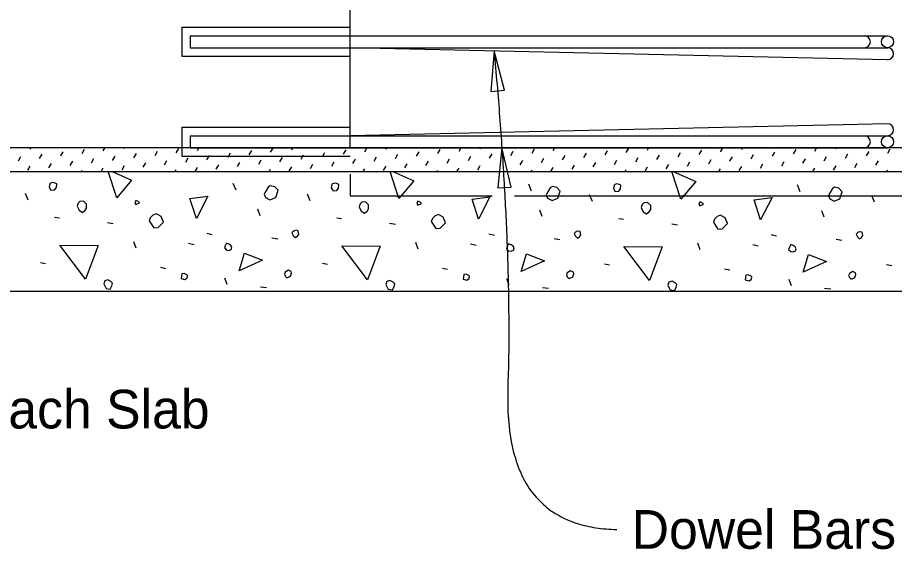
# Model space of a CAD drawing. Extents: x 21665 to 21741.5, y 56121.9 to 56164.2.
# Drawn here: x 21705.4 to 21709.972, y 56139.518 to 56142.347 of the extents above; entities that cross this region are included whole.
import ezdxf

# ---------------------------------------------------------------- set-up
doc = ezdxf.new("R2010")
doc.units = 0
for name, color, linetype in [('Dimension', 7, 'Continuous'), ('ExistSuperStruct', 7, 'Continuous'), ('Miscellaneous', 7, 'Continuous'), ('Rebar', 7, 'Continuous'), ('StrMiscConc', 7, 'Continuous'), ('StrMiscConc_h', 7, 'Continuous'), ('TextStructures', 7, 'Continuous')]:
    doc.layers.add(name, color=color, linetype=linetype)

msp = doc.modelspace()

# ---------------------------------------------------------------- linework, layer by layer
at = {"layer": 'Dimension'}
for points in [[(21707.8847, 56142.1727), (21707.8687, 56141.9621), (21707.939, 56141.9686)], [(21707.9254, 56141.6688), (21707.904, 56141.4586), (21707.9744, 56141.4633)]]:
    msp.add_lwpolyline(points, close=True, dxfattribs=at)
msp.add_open_spline([(21707.8847, 56142.1727), (21707.9806, 56141.1325), (21707.9326, 56139.6921), (21708.5241, 56139.6796)], degree=2, dxfattribs=at)
at = {"layer": 'ExistSuperStruct'}
for p, q in [((21706.2561, 56142.2964), (21706.2561, 56142.145)), ((21706.2561, 56142.2964), (21707.1339, 56142.2964)), ((21706.2561, 56142.145), (21707.1339, 56142.145)), ((21706.2561, 56141.7755), (21706.2561, 56141.6241)), ((21706.2561, 56141.7755), (21707.1339, 56141.7755)), ((21699.1314, 56141.6687), (21711.5431, 56141.6687)), ((21706.2561, 56141.6241), (21707.1339, 56141.6241)), ((21699.1314, 56141.5437), (21711.5431, 56141.5437)), ((21711.5431, 56140.9187), (21704.3514, 56140.9187))]:
    msp.add_line(p, q, dxfattribs=at)
at = {"layer": 'Miscellaneous'}
for p, q in [((21705.4666, 56141.6613), (21705.4709, 56141.6687)), ((21705.7367, 56141.6384), (21705.7496, 56141.6608)), ((21705.8473, 56141.6514), (21705.8574, 56141.6687)), ((21705.9579, 56141.6643), (21705.9605, 56141.6687)), ((21706.228, 56141.6414), (21706.241, 56141.6638)), ((21706.3387, 56141.6544), (21706.347, 56141.6687)), ((21706.4493, 56141.6673), (21706.4501, 56141.6687)), ((21706.7194, 56141.6444), (21706.7324, 56141.6668)), ((21706.83, 56141.6574), (21706.8366, 56141.6687)), ((21707.2108, 56141.6475), (21707.2231, 56141.6687)), ((21707.3214, 56141.6604), (21707.3262, 56141.6687)), ((21707.5915, 56141.6375), (21707.6045, 56141.6599)), ((21707.7021, 56141.6505), (21707.7127, 56141.6687)), ((21707.8128, 56141.6634), (21707.8158, 56141.6687)), ((21708.0829, 56141.6405), (21708.0958, 56141.6629)), ((21708.1935, 56141.6535), (21708.2023, 56141.6687)), ((21708.3041, 56141.6665), (21708.3054, 56141.6687)), ((21708.5742, 56141.6436), (21708.5872, 56141.6659)), ((21708.6849, 56141.6565), (21708.6919, 56141.6687)), ((21709.0656, 56141.6466), (21709.0784, 56141.6687)), ((21709.1762, 56141.6595), (21709.1815, 56141.6687)), ((21709.4463, 56141.6366), (21709.4593, 56141.659)), ((21709.557, 56141.6496), (21709.568, 56141.6687)), ((21709.6676, 56141.6626), (21709.6712, 56141.6687)), ((21709.9377, 56141.6397), (21709.9507, 56141.662)), ((21705.4048, 56141.5995), (21705.4177, 56141.6219)), ((21705.5154, 56141.6125), (21705.5284, 56141.6349)), ((21705.626, 56141.6254), (21705.639, 56141.6478)), ((21705.8961, 56141.6025), (21705.9091, 56141.6249)), ((21706.0068, 56141.6155), (21706.0197, 56141.6379)), ((21706.1174, 56141.6285), (21706.1304, 56141.6508)), ((21706.2769, 56141.5926), (21706.2898, 56141.615)), ((21706.3875, 56141.6055), (21706.4005, 56141.6279)), ((21706.4981, 56141.6185), (21706.5111, 56141.6409)), ((21706.6088, 56141.6315), (21706.6217, 56141.6539)), ((21706.7682, 56141.5956), (21706.7812, 56141.618)), ((21706.8789, 56141.6086), (21706.8918, 56141.631)), ((21706.9895, 56141.6215), (21707.0025, 56141.6439)), ((21707.1001, 56141.6345), (21707.1131, 56141.6569)), ((21707.2596, 56141.5986), (21707.2726, 56141.621)), ((21707.3702, 56141.6116), (21707.3832, 56141.634)), ((21707.4809, 56141.6246), (21707.4938, 56141.6469)), ((21707.751, 56141.6016), (21707.7639, 56141.624)), ((21707.8616, 56141.6146), (21707.8746, 56141.637)), ((21707.9722, 56141.6276), (21707.9852, 56141.65)), ((21708.1317, 56141.5917), (21708.1447, 56141.6141)), ((21708.2423, 56141.6047), (21708.2553, 56141.6271)), ((21708.353, 56141.6176), (21708.3659, 56141.64)), ((21708.4636, 56141.6306), (21708.4766, 56141.653)), ((21708.6231, 56141.5947), (21708.636, 56141.6171)), ((21708.7337, 56141.6077), (21708.7467, 56141.6301)), ((21708.8443, 56141.6206), (21708.8573, 56141.643)), ((21708.955, 56141.6336), (21708.9679, 56141.656)), ((21709.1144, 56141.5977), (21709.1274, 56141.6201)), ((21709.2251, 56141.6107), (21709.238, 56141.6331)), ((21709.3357, 56141.6237), (21709.3487, 56141.6461)), ((21709.6058, 56141.6008), (21709.6188, 56141.6232)), ((21709.7164, 56141.6137), (21709.7294, 56141.6361)), ((21709.8271, 56141.6267), (21709.84, 56141.6491)), ((21705.4536, 56141.5507), (21705.4666, 56141.5731)), ((21705.5642, 56141.5636), (21705.5772, 56141.586)), ((21705.6749, 56141.5766), (21705.6878, 56141.599)), ((21705.7855, 56141.5896), (21705.7985, 56141.612)), ((21705.945, 56141.5537), (21705.9579, 56141.5761)), ((21706.0556, 56141.5667), (21706.0686, 56141.589)), ((21706.1662, 56141.5796), (21706.1792, 56141.602)), ((21706.4363, 56141.5567), (21706.4493, 56141.5791)), ((21706.547, 56141.5697), (21706.5599, 56141.5921)), ((21706.6576, 56141.5826), (21706.6706, 56141.605)), ((21706.8171, 56141.5468), (21706.83, 56141.5692)), ((21706.9277, 56141.5597), (21706.9407, 56141.5821)), ((21707.0383, 56141.5727), (21707.0513, 56141.5951)), ((21707.149, 56141.5857), (21707.1619, 56141.6081)), ((21707.3084, 56141.5498), (21707.3214, 56141.5722)), ((21707.4191, 56141.5628), (21707.432, 56141.5851)), ((21707.5297, 56141.5757), (21707.5427, 56141.5981)), ((21707.6403, 56141.5887), (21707.6533, 56141.6111)), ((21707.7998, 56141.5528), (21707.8128, 56141.5752)), ((21708.0211, 56141.5787), (21708.034, 56141.6011)), ((21708.2912, 56141.5558), (21708.3041, 56141.5782)), ((21708.4018, 56141.5688), (21708.4148, 56141.5912)), ((21708.5124, 56141.5818), (21708.5254, 56141.6041)), ((21708.6719, 56141.5459), (21708.6849, 56141.5683)), ((21708.7825, 56141.5589), (21708.7955, 56141.5812)), ((21708.8932, 56141.5718), (21708.9061, 56141.5942)), ((21709.0038, 56141.5848), (21709.0168, 56141.6072)), ((21709.1633, 56141.5489), (21709.1762, 56141.5713)), ((21709.2739, 56141.5619), (21709.2869, 56141.5843)), ((21709.3845, 56141.5748), (21709.3975, 56141.5972)), ((21709.4952, 56141.5878), (21709.5081, 56141.6102)), ((21709.6546, 56141.5519), (21709.6676, 56141.5743)), ((21709.7653, 56141.5649), (21709.7782, 56141.5873)), ((21709.8759, 56141.5779), (21709.8889, 56141.6002)), ((21705.7329, 56141.5437), (21705.7367, 56141.5502)), ((21705.836, 56141.5437), (21705.8473, 56141.5631)), ((21706.2225, 56141.5437), (21706.228, 56141.5532)), ((21706.3257, 56141.5438), (21706.3387, 56141.5661)), ((21706.7121, 56141.5437), (21706.7194, 56141.5562)), ((21707.0986, 56141.5437), (21707.1001, 56141.5463)), ((21707.2018, 56141.5437), (21707.2108, 56141.5592)), ((21707.5882, 56141.5437), (21707.5915, 56141.5493)), ((21707.6914, 56141.5437), (21707.7021, 56141.5622)), ((21708.0779, 56141.5437), (21708.0829, 56141.5523)), ((21708.181, 56141.5437), (21708.1935, 56141.5653)), ((21708.5675, 56141.5437), (21708.5742, 56141.5553)), ((21708.954, 56141.5437), (21708.955, 56141.5454)), ((21709.0571, 56141.5437), (21709.0656, 56141.5583)), ((21709.4436, 56141.5437), (21709.4463, 56141.5484)), ((21709.5467, 56141.5437), (21709.557, 56141.5614)), ((21709.7372, 56141.5402), (21709.7358, 56141.5437)), ((21709.9332, 56141.5437), (21709.9377, 56141.5514)), ((21706.5396, 56141.4465), (21706.5254, 56141.4818)), ((21708.0798, 56141.4429), (21708.0657, 56141.4783)), ((21705.456, 56141.3953), (21705.4418, 56141.4306)), ((21709.4808, 56141.4394), (21709.4667, 56141.4748)), ((21706.9266, 56141.3918), (21706.9125, 56141.4271)), ((21708.3973, 56141.3882), (21708.3831, 56141.4236)), ((21709.8679, 56141.3847), (21709.8538, 56141.42)), ((21706.6651, 56141.3139), (21706.6527, 56141.3475)), ((21708.1357, 56141.3104), (21708.1233, 56141.3439)), ((21709.6063, 56141.3068), (21709.594, 56141.3404)), ((21705.5939, 56141.3069), (21705.6186, 56141.3034)), ((21707.0645, 56141.3034), (21707.0893, 56141.2998)), ((21708.5351, 56141.2998), (21708.5599, 56141.2963)), ((21705.8696, 56141.2786), (21705.8997, 56141.2733)), ((21707.3403, 56141.2751), (21707.3703, 56141.2698)), ((21708.8109, 56141.2715), (21708.841, 56141.2662)), ((21706.3875, 56141.2237), (21706.4158, 56141.2167)), ((21707.8582, 56141.2202), (21707.8864, 56141.2131)), ((21709.3288, 56141.2167), (21709.3571, 56141.2096)), ((21706.0181, 56141.1443), (21706.0058, 56141.1779)), ((21706.2921, 56141.1708), (21706.3204, 56141.1637)), ((21706.7269, 56141.1991), (21706.7569, 56141.1938)), ((21707.4888, 56141.1407), (21707.4764, 56141.1743)), ((21707.7628, 56141.1672), (21707.7911, 56141.1602)), ((21708.1975, 56141.1955), (21708.2276, 56141.1902)), ((21708.9594, 56141.1372), (21708.947, 56141.1708)), ((21709.2334, 56141.1637), (21709.2617, 56141.1566)), ((21709.6681, 56141.192), (21709.6982, 56141.1867)), ((21705.5196, 56141.07), (21705.5461, 56141.0647)), ((21706.9903, 56141.0665), (21707.0168, 56141.0612)), ((21706.1454, 56141.0453), (21706.1719, 56141.04)), ((21707.6161, 56141.0417), (21707.6426, 56141.0364)), ((21708.4609, 56141.0629), (21708.4874, 56141.0576)), ((21709.0867, 56141.0382), (21709.1132, 56141.0329)), ((21709.9315, 56141.0594), (21709.9581, 56141.0541)), ((21706.4936, 56140.9552), (21706.4812, 56140.9888)), ((21707.9642, 56140.9517), (21707.9519, 56140.9852)), ((21709.4349, 56140.9481), (21709.4225, 56140.9817)), ((21706.6668, 56140.9445), (21706.6986, 56140.941)), ((21708.1374, 56140.941), (21708.1692, 56140.9374)), ((21709.608, 56140.9374), (21709.6399, 56140.9339))]:
    msp.add_line(p, q, dxfattribs=at)
for points in [[(21705.9174, 56141.4077), (21705.8731, 56141.5437)], [(21705.8942, 56141.5437), (21705.9952, 56141.4996), (21705.9174, 56141.4077)], [(21707.388, 56141.4041), (21707.3426, 56141.5437)], [(21707.3567, 56141.5437), (21707.4658, 56141.496), (21707.388, 56141.4041)], [(21708.8586, 56141.4006), (21708.8121, 56141.5437)], [(21708.8193, 56141.5437), (21708.9364, 56141.4925), (21708.8586, 56141.4006)], [(21705.5656, 56141.4625), (21705.5744, 56141.4466), (21705.5939, 56141.4483), (21705.6027, 56141.4607), (21705.6045, 56141.4801), (21705.5921, 56141.4854), (21705.5833, 56141.4872), (21705.5727, 56141.4837), (21705.5691, 56141.4801), (21705.5656, 56141.4625)], [(21707.0362, 56141.4589), (21707.0451, 56141.443), (21707.0645, 56141.4448), (21707.0733, 56141.4572), (21707.0751, 56141.4766), (21707.0627, 56141.4819), (21707.0539, 56141.4837), (21707.0433, 56141.4801), (21707.0398, 56141.4766), (21707.0362, 56141.4589)], [(21708.5069, 56141.4554), (21708.5157, 56141.4395), (21708.5351, 56141.4412), (21708.544, 56141.4536), (21708.5458, 56141.4731), (21708.5334, 56141.4784), (21708.5245, 56141.4801), (21708.5139, 56141.4766), (21708.5104, 56141.4731), (21708.5069, 56141.4554)], [(21706.6934, 56141.4094), (21706.7163, 56141.397), (21706.7464, 56141.4094), (21706.7588, 56141.4465), (21706.7411, 56141.4642), (21706.7181, 56141.4695), (21706.7075, 56141.4624), (21706.6951, 56141.4429), (21706.6863, 56141.427), (21706.6934, 56141.4094)], [(21708.164, 56141.4058), (21708.187, 56141.3934), (21708.217, 56141.4058), (21708.2294, 56141.4429), (21708.2117, 56141.4606), (21708.1887, 56141.4659), (21708.1781, 56141.4589), (21708.1658, 56141.4394), (21708.1569, 56141.4235), (21708.164, 56141.4058)], [(21709.6346, 56141.4023), (21709.6576, 56141.3899), (21709.6877, 56141.4023), (21709.7, 56141.4394), (21709.6824, 56141.4571), (21709.6594, 56141.4624), (21709.6488, 56141.4553), (21709.6364, 56141.4359), (21709.6276, 56141.42), (21709.6346, 56141.4023)], [(21705.7105, 56141.3635), (21705.7212, 56141.3423), (21705.7388, 56141.3316), (21705.753, 56141.3423), (21705.76, 56141.3529), (21705.76, 56141.3741), (21705.7441, 56141.39), (21705.7247, 56141.3882), (21705.7159, 56141.3794), (21705.7105, 56141.3635)], [(21706.0164, 56141.3723), (21706.0358, 56141.3811), (21706.0287, 56141.3882), (21706.0164, 56141.3935), (21706.0111, 56141.3811), (21706.0164, 56141.3723)], [(21706.3327, 56141.2998), (21706.2991, 56141.4041), (21706.3928, 56141.4164), (21706.3327, 56141.2998)], [(21707.1812, 56141.3599), (21707.1918, 56141.3387), (21707.2095, 56141.3281), (21707.2236, 56141.3387), (21707.2307, 56141.3493), (21707.2307, 56141.3705), (21707.2148, 56141.3864), (21707.1953, 56141.3847), (21707.1865, 56141.3758), (21707.1812, 56141.3599)], [(21707.487, 56141.3688), (21707.5065, 56141.3776), (21707.4994, 56141.3847), (21707.487, 56141.39), (21707.4817, 56141.3776), (21707.487, 56141.3688)], [(21707.8034, 56141.2962), (21707.7698, 56141.4005), (21707.8635, 56141.4129), (21707.8034, 56141.2962)], [(21708.9576, 56141.3652), (21708.9771, 56141.3741), (21708.97, 56141.3811), (21708.9576, 56141.3864), (21708.9523, 56141.3741), (21708.9576, 56141.3652)], [(21709.274, 56141.2927), (21709.2404, 56141.397), (21709.3341, 56141.4094), (21709.274, 56141.2927)], [(21708.6518, 56141.3564), (21708.6624, 56141.3352), (21708.6801, 56141.3246), (21708.6942, 56141.3352), (21708.7013, 56141.3458), (21708.7013, 56141.367), (21708.6854, 56141.3829), (21708.666, 56141.3811), (21708.6571, 56141.3723), (21708.6518, 56141.3564)], [(21706.0871, 56141.2875), (21706.1101, 56141.2503), (21706.133, 56141.2521), (21706.1419, 56141.2609), (21706.1613, 56141.2804), (21706.149, 56141.3104), (21706.1242, 56141.3246), (21706.1065, 56141.3175), (21706.0924, 56141.3034), (21706.0871, 56141.2875)], [(21707.5577, 56141.2839), (21707.5807, 56141.2468), (21707.6037, 56141.2486), (21707.6125, 56141.2574), (21707.632, 56141.2768), (21707.6196, 56141.3069), (21707.5948, 56141.321), (21707.5772, 56141.314), (21707.563, 56141.2998), (21707.5577, 56141.2839)], [(21709.0284, 56141.2804), (21709.0513, 56141.2433), (21709.0743, 56141.245), (21709.0832, 56141.2539), (21709.1026, 56141.2733), (21709.0902, 56141.3034), (21709.0655, 56141.3175), (21709.0478, 56141.3104), (21709.0337, 56141.2963), (21709.0284, 56141.2804)], [(21706.8382, 56141.2114), (21706.8488, 56141.2008), (21706.8595, 56141.2079), (21706.8665, 56141.2185), (21706.863, 56141.2362), (21706.8541, 56141.238), (21706.8418, 56141.2362), (21706.8312, 56141.2256), (21706.8382, 56141.2114)], [(21708.3089, 56141.2079), (21708.3195, 56141.1973), (21708.3301, 56141.2044), (21708.3372, 56141.215), (21708.3336, 56141.2327), (21708.3248, 56141.2344), (21708.3124, 56141.2327), (21708.3018, 56141.222), (21708.3089, 56141.2079)], [(21709.7795, 56141.2044), (21709.7901, 56141.1938), (21709.8007, 56141.2008), (21709.8078, 56141.2114), (21709.8043, 56141.2291), (21709.7954, 56141.2309), (21709.783, 56141.2291), (21709.7724, 56141.2185), (21709.7795, 56141.2044)], [(21705.7547, 56140.9834), (21705.6204, 56141.1602), (21705.8202, 56141.1584), (21705.7547, 56140.9834)], [(21706.4901, 56141.1354), (21706.5024, 56141.1336), (21706.5148, 56141.1389), (21706.5183, 56141.1495), (21706.513, 56141.1583), (21706.5024, 56141.1654), (21706.4901, 56141.1707), (21706.483, 56141.1566), (21706.4795, 56141.146), (21706.4901, 56141.1354)], [(21707.2254, 56140.9799), (21707.091, 56141.1566), (21707.2908, 56141.1549), (21707.2254, 56140.9799)], [(21707.9607, 56141.1318), (21707.9731, 56141.13), (21707.9854, 56141.1354), (21707.989, 56141.146), (21707.9837, 56141.1548), (21707.9731, 56141.1619), (21707.9607, 56141.1672), (21707.9536, 56141.153), (21707.9501, 56141.1424), (21707.9607, 56141.1318)], [(21709.4313, 56141.1283), (21709.4437, 56141.1265), (21709.4561, 56141.1318), (21709.4596, 56141.1424), (21709.4543, 56141.1513), (21709.4437, 56141.1583), (21709.4313, 56141.1636), (21709.4243, 56141.1495), (21709.4207, 56141.1389), (21709.4313, 56141.1283)], [(21706.5554, 56141.0276), (21706.5837, 56141.1195), (21706.6774, 56141.0824), (21706.5554, 56141.0276)], [(21708.026, 56141.0241), (21708.0543, 56141.116), (21708.148, 56141.0789), (21708.026, 56141.0241)], [(21708.696, 56140.9763), (21708.5617, 56141.1531), (21708.7614, 56141.1513), (21708.696, 56140.9763)], [(21709.4967, 56141.0205), (21709.5249, 56141.1124), (21709.6186, 56141.0753), (21709.4967, 56141.0205)], [(21706.8029, 56140.9922), (21706.81, 56140.9922), (21706.8241, 56140.9993), (21706.8294, 56141.0152), (21706.8276, 56141.0241), (21706.8135, 56141.0311), (21706.7958, 56141.0205), (21706.7923, 56141.0099), (21706.7958, 56140.9993), (21706.8029, 56140.9922)], [(21708.2735, 56140.9887), (21708.2806, 56140.9887), (21708.2947, 56140.9958), (21708.3, 56141.0117), (21708.2983, 56141.0205), (21708.2841, 56141.0276), (21708.2664, 56141.017), (21708.2629, 56141.0064), (21708.2664, 56140.9958), (21708.2735, 56140.9887)], [(21709.7442, 56140.9852), (21709.7512, 56140.9852), (21709.7654, 56140.9922), (21709.7707, 56141.0081), (21709.7689, 56141.017), (21709.7548, 56141.0241), (21709.7371, 56141.0134), (21709.7335, 56141.0028), (21709.7371, 56140.9922), (21709.7442, 56140.9852)], [(21705.8537, 56140.9516), (21705.8626, 56140.9357), (21705.8838, 56140.9321), (21705.8926, 56140.948), (21705.8962, 56140.9622), (21705.8873, 56140.971), (21705.8714, 56140.9799), (21705.8555, 56140.9746), (21705.8502, 56140.9586), (21705.8537, 56140.9516)], [(21706.2533, 56140.9869), (21706.2727, 56140.9816), (21706.2851, 56140.9905), (21706.2868, 56141.0028), (21706.2833, 56141.0064), (21706.2692, 56141.0134), (21706.2568, 56141.0117), (21706.255, 56140.9993), (21706.2533, 56140.9869)], [(21707.3244, 56140.948), (21707.3332, 56140.9321), (21707.3544, 56140.9286), (21707.3633, 56140.9445), (21707.3668, 56140.9586), (21707.358, 56140.9675), (21707.3421, 56140.9763), (21707.3261, 56140.971), (21707.3208, 56140.9551), (21707.3244, 56140.948)], [(21707.7239, 56140.9834), (21707.7433, 56140.9781), (21707.7557, 56140.9869), (21707.7575, 56140.9993), (21707.7539, 56141.0028), (21707.7398, 56141.0099), (21707.7274, 56141.0081), (21707.7257, 56140.9958), (21707.7239, 56140.9834)], [(21709.1945, 56140.9799), (21709.214, 56140.9746), (21709.2263, 56140.9834), (21709.2281, 56140.9958), (21709.2246, 56140.9993), (21709.2104, 56141.0064), (21709.1981, 56141.0046), (21709.1963, 56140.9922), (21709.1945, 56140.9799)], [(21708.795, 56140.9445), (21708.8038, 56140.9286), (21708.8251, 56140.9251), (21708.8339, 56140.941), (21708.8374, 56140.9551), (21708.8286, 56140.964), (21708.8127, 56140.9728), (21708.7968, 56140.9675), (21708.7915, 56140.9516), (21708.795, 56140.9445)]]:
    msp.add_lwpolyline(points, dxfattribs=at)
at = {"layer": 'Rebar'}
for p, q in [((21706.3005, 56142.2519), (21709.936, 56142.2519)), ((21706.3005, 56142.2519), (21706.3005, 56142.1894)), ((21706.3005, 56142.1894), (21709.936, 56142.1894)), ((21709.936, 56142.127), (21707.1339, 56142.1894)), ((21709.936, 56141.7935), (21707.1339, 56141.7311)), ((21706.3005, 56141.7311), (21709.936, 56141.7311)), ((21706.3005, 56141.7311), (21706.3005, 56141.6686)), ((21706.3005, 56141.6686), (21709.936, 56141.6686))]:
    msp.add_line(p, q, dxfattribs=at)
for centre in [(21709.936, 56142.2206), (21709.936, 56141.6998)]:
    msp.add_circle(centre, 0.0312, dxfattribs=at)
for centre in [(21709.8157, 56142.2207), (21709.936, 56142.1582), (21709.936, 56141.7623), (21709.8157, 56141.6999)]:
    msp.add_arc(centre, 0.0312, 270, 90, dxfattribs=at)
at = {"layer": 'StrMiscConc'}
msp.add_line((21707.1339, 56141.6687), (21707.1339, 56142.4186), dxfattribs=at)
at = {"layer": 'StrMiscConc_h'}
for p, q in [((21707.1339, 56141.531), (21707.1339, 56141.4186)), ((21707.1339, 56141.4186), (21707.875, 56141.4186)), ((21707.9922, 56141.4186), (21710.1339, 56141.4186))]:
    msp.add_line(p, q, dxfattribs=at)

# ---------------------------------------------------------------- texts
at = {"layer": 'Dimension'}
msp.add_text('Dowel Bars 4L (10" ', height=0.2016, dxfattribs=at).set_placement((21708.6024, 56139.5788))
at = {"layer": 'TextStructures'}
msp.add_text('Existing Approach Slab', height=0.2016, dxfattribs=at).set_placement((21703.6143, 56140.2058))

doc.saveas('drawing.dxf')
